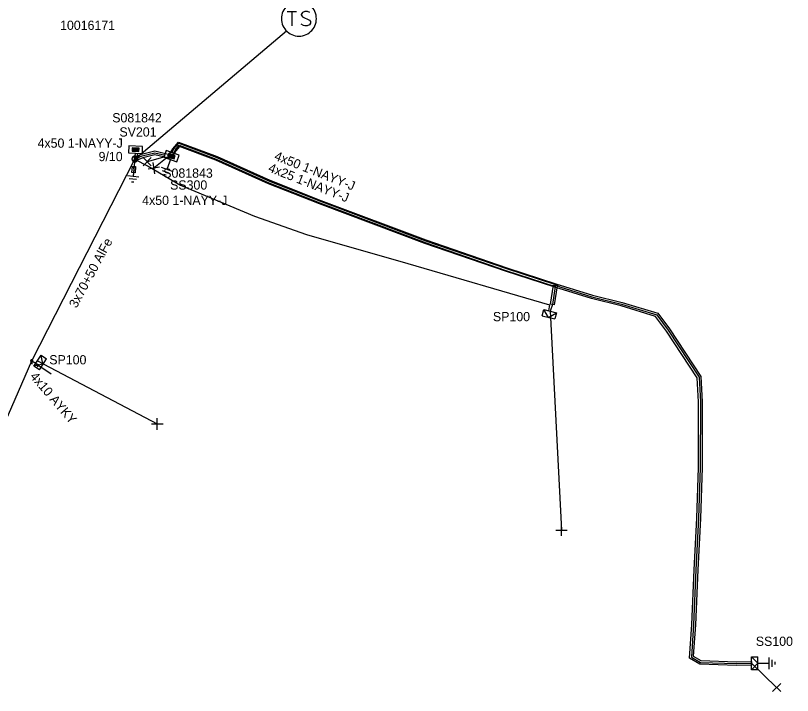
# Model space of a CAD drawing. Extents: x -717562 to -713845, y -1151196 to -1143903.
# Drawn here: x -717097.2 to -717013.1, y -1144090.6 to -1144017.1 of the extents above; entities that cross this region are included whole.
import ezdxf

# ---------------------------------------------------------------- set-up
doc = ezdxf.new("R2010")
doc.units = 0
for name, color, linetype in [('Vrstva 1', 7, 'Continuous'), ('Vrstva 12', 7, 'Continuous'), ('Vrstva 13', 7, 'Continuous'), ('Vrstva 14', 7, 'Continuous'), ('Vrstva 15', 7, 'Continuous'), ('Vrstva 16', 7, 'Continuous'), ('Vrstva 2', 7, 'Continuous'), ('Vrstva 20', 7, 'Continuous'), ('Vrstva 25', 7, 'Continuous'), ('Vrstva 26', 7, 'Continuous'), ('Vrstva 28', 7, 'Continuous'), ('Vrstva 29', 7, 'Continuous'), ('Vrstva 30', 7, 'Continuous'), ('Vrstva 31', 7, 'Continuous'), ('Vrstva 33', 7, 'Continuous'), ('Vrstva 34', 7, 'Continuous'), ('Vrstva 5', 7, 'Continuous'), ('Vrstva 52', 7, 'Continuous'), ('Vrstva 54', 7, 'Continuous'), ('Vrstva 59', 7, 'Continuous'), ('Vrstva 6', 7, 'Continuous'), ('Vrstva 8', 7, 'Continuous'), ('Vrstva 9', 7, 'Continuous')]:
    doc.layers.add(name, color=color, linetype=linetype)

# ---------------------------------------------------------------- blocks, each defined once
blk = doc.blocks.new('NN440')
at = {"layer": 'Vrstva 2'}
for points in [[(0.63, 0), (0.63, 0.06), (0.62, 0.13), (0.6, 0.19), (0.58, 0.25), (0.55, 0.31), (0.51, 0.37), (0.47, 0.42), (0.42, 0.46), (0.37, 0.51), (0.32, 0.54), (0.26, 0.57), (0.2, 0.59), (0.13, 0.61), (0.07, 0.62), (0, 0.63), (-0.06, 0.62), (-0.13, 0.61), (-0.19, 0.59), (-0.26, 0.57), (-0.31, 0.54), (-0.37, 0.51), (-0.42, 0.46), (-0.47, 0.42), (-0.51, 0.37), (-0.54, 0.31), (-0.57, 0.25), (-0.6, 0.19), (-0.62, 0.13), (-0.63, 0.06), (-0.63, 0), (-0.63, -0.07), (-0.62, -0.14), (-0.6, -0.2), (-0.57, -0.26), (-0.54, -0.32), (-0.51, -0.37), (-0.47, -0.43), (-0.42, -0.47), (-0.37, -0.51), (-0.31, -0.55), (-0.26, -0.58), (-0.19, -0.6), (-0.13, -0.62), (-0.06, -0.63), (0, -0.63), (0.07, -0.63), (0.13, -0.62), (0.2, -0.6), (0.26, -0.58), (0.32, -0.55), (0.37, -0.51), (0.42, -0.47), (0.47, -0.43), (0.51, -0.37), (0.55, -0.32), (0.58, -0.26), (0.6, -0.2), (0.62, -0.14), (0.63, -0.07), (0.63, 0)], [(-0.63, 0), (0.63, 0)], [(-0.6, -0.18), (0.57, -0.18)], [(-0.51, -0.32), (0.5, -0.32)], [(-0.37, -0.47), (0.35, -0.47)]]:
    blk.add_lwpolyline(points, dxfattribs=at)
blk = doc.blocks.new('NN565')
at = {"layer": 'Vrstva 2'}
for points in [[(0.015, 0.528), (0.015, 2.528)], [(0.157, 0.937), (0.015, 0.528), (-0.119, 0.937)]]:
    blk.add_lwpolyline(points, dxfattribs=at)
blk = doc.blocks.new('NN800')
at = {"layer": 'Vrstva 1'}
for points in [[(-0.442, 0.442), (0.442, -0.442)], [(-0.442, -0.442), (0.442, 0.442)]]:
    blk.add_lwpolyline(points, dxfattribs=at)
blk = doc.blocks.new('NN820')
at = {"layer": 'Vrstva 13'}
for points in [[(-0.003, 0.004), (-0.003, -1.049)], [(-0.165, -0.813), (0.165, -0.813)], [(-0.165, -1.473), (-0.165, -0.813)], [(0.165, -0.813), (0.165, -1.473)], [(0.165, -1.473), (-0.165, -1.473)], [(-0.003, -1.049), (-0.062, -0.926)], [(-0.003, -1.049), (0.057, -0.926)], [(-0.003, -1.473), (-0.003, -1.871)]]:
    blk.add_lwpolyline(points, dxfattribs=at)
blk = doc.blocks.new('NN620')
at = {"layer": 'Vrstva 8'}
for points in [[(0.752, 0.004), (-0.748, 0.004)], [(-0.748, 0.004), (-0.748, -0.746)], [(0.752, -0.746), (0.752, 0.004)], [(-0.748, -0.746), (0.752, -0.746)], [(0.368, -0.18), (-0.376, -0.18)], [(-0.376, -0.18), (-0.376, -0.558)], [(-0.376, -0.558), (0.368, -0.558)], [(0.321, -0.227), (-0.329, -0.227)], [(-0.329, -0.227), (-0.329, -0.51)], [(-0.329, -0.51), (0.321, -0.51)], [(0.274, -0.274), (-0.281, -0.274)], [(-0.281, -0.274), (-0.281, -0.463)], [(-0.281, -0.463), (0.274, -0.463)], [(0.227, -0.321), (-0.234, -0.321)], [(-0.234, -0.321), (-0.234, -0.416)], [(-0.234, -0.416), (0.227, -0.416)], [(-0.193, -0.369), (0.185, -0.369)], [(0.227, -0.416), (0.227, -0.321)], [(0.274, -0.463), (0.274, -0.274)], [(0.321, -0.51), (0.321, -0.227)], [(0.368, -0.558), (0.368, -0.18)]]:
    blk.add_lwpolyline(points, dxfattribs=at)
blk = doc.blocks.new('NN630')
at = {"layer": 'Vrstva 9'}
for points in [[(-0.003, -0.7), (-0.703, 0)], [(-0.703, -0.7), (-0.703, 0), (0.697, 0), (0.697, -0.7)], [(-0.703, -0.7), (0.697, -0.7)], [(-0.003, -0.7), (0.697, 0)]]:
    blk.add_lwpolyline(points, dxfattribs=at)
blk = doc.blocks.new('NN810')
at = {"layer": 'Vrstva 14'}
for points in [[(0.004, -0.64), (0.004, -1.89)], [(0.629, -1.89), (-0.621, -1.89)], [(0.388, -2.2), (-0.399, -2.2)], [(0.004, -2.515), (-0.124, -2.515)], [(0.137, -2.515), (0.004, -2.515)]]:
    blk.add_lwpolyline(points, dxfattribs=at)
blk = doc.blocks.new('NN500')
at = {"layer": 'Vrstva 2'}
for points in [[(0, -0.24), (0.02, -0.23), (0.05, -0.23), (0.07, -0.22), (0.09, -0.22), (0.12, -0.2), (0.14, -0.19), (0.16, -0.18), (0.17, -0.16), (0.19, -0.14), (0.2, -0.12), (0.21, -0.1), (0.22, -0.07), (0.23, -0.05), (0.23, -0.02), (0.23, 0), (0.23, 0.02), (0.23, 0.05), (0.22, 0.07), (0.21, 0.1), (0.2, 0.12), (0.19, 0.14), (0.17, 0.16), (0.16, 0.17), (0.14, 0.19), (0.12, 0.2), (0.09, 0.21), (0.07, 0.22), (0.05, 0.23), (0.02, 0.23), (0, 0.23), (-0.03, 0.23), (-0.05, 0.23), (-0.07, 0.22), (-0.1, 0.21), (-0.12, 0.2), (-0.14, 0.19), (-0.16, 0.17), (-0.18, 0.16), (-0.19, 0.14), (-0.2, 0.12), (-0.22, 0.1), (-0.22, 0.07), (-0.23, 0.05), (-0.23, 0.02), (-0.24, 0), (-0.23, -0.02), (-0.23, -0.05), (-0.22, -0.07), (-0.22, -0.1), (-0.2, -0.12), (-0.19, -0.14), (-0.18, -0.16), (-0.16, -0.18), (-0.14, -0.19), (-0.12, -0.2), (-0.1, -0.22), (-0.07, -0.22), (-0.05, -0.23), (-0.03, -0.23), (0, -0.24)], [(0, -0.24), (0.02, -0.23), (0.05, -0.23), (0.07, -0.22), (0.09, -0.22), (0.12, -0.2), (0.14, -0.19), (0.16, -0.18), (0.17, -0.16), (0.19, -0.14), (0.2, -0.12), (0.21, -0.1), (0.22, -0.07), (0.23, -0.05), (0.23, -0.02), (0.23, 0), (0.23, 0.02), (0.23, 0.05), (0.22, 0.07), (0.21, 0.1), (0.2, 0.12), (0.19, 0.14), (0.17, 0.16), (0.16, 0.17), (0.14, 0.19), (0.12, 0.2), (0.09, 0.21), (0.07, 0.22), (0.05, 0.23), (0.02, 0.23), (0, 0.23), (-0.03, 0.23), (-0.05, 0.23), (-0.07, 0.22), (-0.1, 0.21), (-0.12, 0.2), (-0.14, 0.19), (-0.16, 0.17), (-0.18, 0.16), (-0.19, 0.14), (-0.2, 0.12), (-0.22, 0.1), (-0.22, 0.07), (-0.23, 0.05), (-0.23, 0.02), (-0.24, 0), (-0.23, -0.02), (-0.23, -0.05), (-0.22, -0.07), (-0.22, -0.1), (-0.2, -0.12), (-0.19, -0.14), (-0.18, -0.16), (-0.16, -0.18), (-0.14, -0.19), (-0.12, -0.2), (-0.1, -0.22), (-0.07, -0.22), (-0.05, -0.23), (-0.03, -0.23), (0, -0.24)], [(0, -0.21), (0.02, -0.2), (0.04, -0.2), (0.06, -0.2), (0.08, -0.19), (0.1, -0.18), (0.12, -0.17), (0.14, -0.15), (0.15, -0.14), (0.16, -0.12), (0.18, -0.1), (0.19, -0.08), (0.19, -0.06), (0.2, -0.04), (0.2, -0.02), (0.2, 0), (0.2, 0.02), (0.2, 0.04), (0.19, 0.06), (0.19, 0.08), (0.18, 0.1), (0.16, 0.12), (0.15, 0.14), (0.14, 0.15), (0.12, 0.17), (0.1, 0.18), (0.08, 0.19), (0.06, 0.19), (0.04, 0.2), (0.02, 0.2), (0, 0.2), (-0.02, 0.2), (-0.04, 0.2), (-0.06, 0.19), (-0.08, 0.19), (-0.1, 0.18), (-0.12, 0.17), (-0.14, 0.15), (-0.15, 0.14), (-0.17, 0.12), (-0.18, 0.1), (-0.19, 0.08), (-0.2, 0.06), (-0.2, 0.04), (-0.21, 0.02), (-0.21, 0), (-0.21, -0.02), (-0.2, -0.04), (-0.2, -0.06), (-0.19, -0.08), (-0.18, -0.1), (-0.17, -0.12), (-0.15, -0.14), (-0.14, -0.15), (-0.12, -0.17), (-0.1, -0.18), (-0.08, -0.19), (-0.06, -0.2), (-0.04, -0.2), (-0.02, -0.2), (0, -0.21)], [(0, -0.18), (0.02, -0.18), (0.04, -0.17), (0.05, -0.17), (0.07, -0.16), (0.09, -0.15), (0.1, -0.14), (0.12, -0.13), (0.13, -0.12), (0.14, -0.1), (0.15, -0.09), (0.16, -0.07), (0.17, -0.05), (0.17, -0.04), (0.17, -0.02), (0.17, 0), (0.17, 0.02), (0.17, 0.04), (0.17, 0.05), (0.16, 0.07), (0.15, 0.09), (0.14, 0.1), (0.13, 0.12), (0.12, 0.13), (0.1, 0.14), (0.09, 0.15), (0.07, 0.16), (0.05, 0.17), (0.04, 0.17), (0.02, 0.17), (0, 0.18), (-0.02, 0.17), (-0.04, 0.17), (-0.06, 0.17), (-0.07, 0.16), (-0.09, 0.15), (-0.1, 0.14), (-0.12, 0.13), (-0.13, 0.12), (-0.14, 0.1), (-0.15, 0.09), (-0.16, 0.07), (-0.17, 0.05), (-0.17, 0.04), (-0.18, 0.02), (-0.18, 0), (-0.18, -0.02), (-0.17, -0.04), (-0.17, -0.05), (-0.16, -0.07), (-0.15, -0.09), (-0.14, -0.1), (-0.13, -0.12), (-0.12, -0.13), (-0.1, -0.14), (-0.09, -0.15), (-0.07, -0.16), (-0.06, -0.17), (-0.04, -0.17), (-0.02, -0.18), (0, -0.18)], [(0, -0.15), (0.01, -0.15), (0.03, -0.14), (0.04, -0.14), (0.06, -0.13), (0.07, -0.13), (0.08, -0.12), (0.1, -0.11), (0.11, -0.1), (0.12, -0.09), (0.13, -0.07), (0.13, -0.06), (0.14, -0.05), (0.14, -0.03), (0.14, -0.02), (0.14, 0), (0.14, 0.01), (0.14, 0.03), (0.14, 0.04), (0.13, 0.06), (0.13, 0.07), (0.12, 0.09), (0.11, 0.1), (0.1, 0.11), (0.08, 0.12), (0.07, 0.13), (0.06, 0.13), (0.04, 0.14), (0.03, 0.14), (0.01, 0.14), (0, 0.15), (-0.02, 0.14), (-0.03, 0.14), (-0.05, 0.14), (-0.06, 0.13), (-0.07, 0.13), (-0.09, 0.12), (-0.1, 0.11), (-0.11, 0.1), (-0.12, 0.09), (-0.13, 0.07), (-0.13, 0.06), (-0.14, 0.04), (-0.14, 0.03), (-0.15, 0.01), (-0.15, 0), (-0.15, -0.02), (-0.14, -0.03), (-0.14, -0.05), (-0.13, -0.06), (-0.13, -0.07), (-0.12, -0.09), (-0.11, -0.1), (-0.1, -0.11), (-0.09, -0.12), (-0.07, -0.13), (-0.06, -0.13), (-0.05, -0.14), (-0.03, -0.14), (-0.02, -0.15), (0, -0.15)], [(0, -0.12), (0.01, -0.12), (0.02, -0.11), (0.03, -0.11), (0.05, -0.11), (0.06, -0.1), (0.07, -0.09), (0.08, -0.09), (0.09, -0.08), (0.09, -0.07), (0.1, -0.06), (0.11, -0.05), (0.11, -0.04), (0.11, -0.02), (0.11, -0.01), (0.12, 0), (0.11, 0.01), (0.11, 0.02), (0.11, 0.04), (0.11, 0.05), (0.1, 0.06), (0.09, 0.07), (0.09, 0.08), (0.08, 0.09), (0.07, 0.09), (0.06, 0.1), (0.05, 0.11), (0.03, 0.11), (0.02, 0.11), (0.01, 0.12), (0, 0.12), (-0.01, 0.12), (-0.03, 0.11), (-0.04, 0.11), (-0.05, 0.11), (-0.06, 0.1), (-0.07, 0.09), (-0.08, 0.09), (-0.09, 0.08), (-0.1, 0.07), (-0.1, 0.06), (-0.11, 0.05), (-0.11, 0.04), (-0.12, 0.02), (-0.12, 0.01), (-0.12, 0), (-0.12, -0.01), (-0.12, -0.02), (-0.11, -0.04), (-0.11, -0.05), (-0.1, -0.06), (-0.1, -0.07), (-0.09, -0.08), (-0.08, -0.09), (-0.07, -0.09), (-0.06, -0.1), (-0.05, -0.11), (-0.04, -0.11), (-0.03, -0.11), (-0.01, -0.12), (0, -0.12)], [(0, -0.09), (0.01, -0.09), (0.02, -0.09), (0.03, -0.08), (0.03, -0.08), (0.04, -0.08), (0.05, -0.07), (0.06, -0.07), (0.06, -0.06), (0.07, -0.05), (0.07, -0.04), (0.08, -0.04), (0.08, -0.03), (0.08, -0.02), (0.09, -0.01), (0.09, 0), (0.09, 0.01), (0.08, 0.02), (0.08, 0.03), (0.08, 0.03), (0.07, 0.04), (0.07, 0.05), (0.06, 0.06), (0.06, 0.06), (0.05, 0.07), (0.04, 0.07), (0.03, 0.08), (0.03, 0.08), (0.02, 0.08), (0.01, 0.09), (0, 0.09), (-0.01, 0.09), (-0.02, 0.08), (-0.03, 0.08), (-0.04, 0.08), (-0.04, 0.07), (-0.05, 0.07), (-0.06, 0.06), (-0.07, 0.06), (-0.07, 0.05), (-0.08, 0.04), (-0.08, 0.03), (-0.08, 0.03), (-0.09, 0.02), (-0.09, 0.01), (-0.09, 0), (-0.09, -0.01), (-0.09, -0.02), (-0.08, -0.03), (-0.08, -0.04), (-0.08, -0.04), (-0.07, -0.05), (-0.07, -0.06), (-0.06, -0.07), (-0.05, -0.07), (-0.04, -0.08), (-0.04, -0.08), (-0.03, -0.08), (-0.02, -0.09), (-0.01, -0.09), (0, -0.09)], [(0, -0.06), (0, -0.06), (0.01, -0.06), (0.02, -0.05), (0.02, -0.05), (0.03, -0.05), (0.03, -0.05), (0.04, -0.04), (0.04, -0.04), (0.05, -0.03), (0.05, -0.03), (0.05, -0.02), (0.05, -0.02), (0.05, -0.01), (0.06, -0.01), (0.06, 0), (0.06, 0.01), (0.05, 0.01), (0.05, 0.02), (0.05, 0.02), (0.05, 0.03), (0.05, 0.03), (0.04, 0.04), (0.04, 0.04), (0.03, 0.05), (0.03, 0.05), (0.02, 0.05), (0.02, 0.05), (0.01, 0.06), (0, 0.06), (0, 0.06), (-0.01, 0.06), (-0.01, 0.06), (-0.02, 0.05), (-0.02, 0.05), (-0.03, 0.05), (-0.03, 0.05), (-0.04, 0.04), (-0.04, 0.04), (-0.05, 0.03), (-0.05, 0.03), (-0.05, 0.02), (-0.06, 0.02), (-0.06, 0.01), (-0.06, 0.01), (-0.06, 0), (-0.06, -0.01), (-0.06, -0.01), (-0.06, -0.02), (-0.05, -0.02), (-0.05, -0.03), (-0.05, -0.03), (-0.04, -0.04), (-0.04, -0.04), (-0.03, -0.05), (-0.03, -0.05), (-0.02, -0.05), (-0.02, -0.05), (-0.01, -0.06), (-0.01, -0.06), (0, -0.06)], [(0, -0.03), (0, -0.03), (0, -0.03), (0.01, -0.03), (0.01, -0.03), (0.01, -0.02), (0.02, -0.02), (0.02, -0.02), (0.02, -0.02), (0.02, -0.02), (0.02, -0.01), (0.02, -0.01), (0.03, -0.01), (0.03, -0.01), (0.03, 0), (0.03, 0), (0.03, 0), (0.03, 0.01), (0.03, 0.01), (0.02, 0.01), (0.02, 0.01), (0.02, 0.02), (0.02, 0.02), (0.02, 0.02), (0.02, 0.02), (0.01, 0.02), (0.01, 0.02), (0.01, 0.03), (0, 0.03), (0, 0.03), (0, 0.03), (0, 0.03), (-0.01, 0.03), (-0.01, 0.03), (-0.01, 0.02), (-0.02, 0.02), (-0.02, 0.02), (-0.02, 0.02), (-0.02, 0.02), (-0.02, 0.02), (-0.03, 0.01), (-0.03, 0.01), (-0.03, 0.01), (-0.03, 0.01), (-0.03, 0), (-0.03, 0), (-0.03, 0), (-0.03, -0.01), (-0.03, -0.01), (-0.03, -0.01), (-0.03, -0.01), (-0.02, -0.02), (-0.02, -0.02), (-0.02, -0.02), (-0.02, -0.02), (-0.02, -0.02), (-0.01, -0.03), (-0.01, -0.03), (-0.01, -0.03), (0, -0.03), (0, -0.03)], [(0.23, 0), (0.7, 0)]]:
    blk.add_lwpolyline(points, dxfattribs=at)
blk = doc.blocks.new('NN610')
at = {"layer": 'Vrstva 6'}
for points in [[(1.883, -0.001), (1.872, 0.196), (1.841, 0.392), (1.79, 0.583), (1.718, 0.768), (1.629, 0.943), (1.521, 1.109), (1.397, 1.263), (1.257, 1.403), (1.103, 1.527), (0.937, 1.635), (0.761, 1.725), (0.577, 1.796), (0.19, 1.878), (0.19, 1.878), (-0.007, 1.889), (-0.205, 1.878), (-0.401, 1.847), (-0.591, 1.796), (-0.777, 1.725), (-0.952, 1.635), (-1.118, 1.527), (-1.272, 1.403), (-1.412, 1.263), (-1.536, 1.109), (-1.644, 0.943), (-1.734, 0.768), (-1.805, 0.583), (-1.856, 0.392), (-1.887, 0.196), (-1.898, -0.001), (-1.887, -0.199), (-1.856, -0.395), (-1.805, -0.585), (-1.734, -0.77), (-1.644, -0.946), (-1.536, -1.112), (-1.411, -1.266), (-1.272, -1.405), (-1.118, -1.53), (-0.952, -1.638), (-0.776, -1.728), (-0.591, -1.799), (-0.401, -1.85), (-0.205, -1.881), (-0.007, -1.892), (0.19, -1.881), (0.385, -1.85), (0.577, -1.799), (0.761, -1.728), (0.937, -1.638), (1.103, -1.53), (1.257, -1.405), (1.397, -1.266), (1.521, -1.112), (1.629, -0.946), (1.718, -0.77), (1.79, -0.585), (1.841, -0.395), (1.872, -0.199), (1.883, -0.001)], [(-1.269, 0.782), (-0.261, 0.782)], [(-0.765, 0.782), (-0.765, -0.792)], [(1.188, 0.656), (0.936, 0.782), (0.621, 0.782), (0.369, 0.656), (0.243, 0.468), (0.243, 0.404), (0.369, 0.216), (1.125, -0.162), (1.251, -0.32), (1.251, -0.478), (1.125, -0.666), (0.873, -0.792), (0.621, -0.792), (0.495, -0.73), (0.243, -0.604)]]:
    blk.add_lwpolyline(points, dxfattribs=at)

msp = doc.modelspace()

# ---------------------------------------------------------------- linework, layer by layer
at = {"layer": 'Vrstva 1'}
for points in [[(-717084.26, -1144032.61), (-717067.847, -1144018.739)], [(-717137.335, -1144242.834), (-717130.537, -1144206.049), (-717125.876, -1144182.429), (-717122.246, -1144158.029), (-717113.166, -1144120.769), (-717112.247, -1144091.459), (-717102.297, -1144070.179), (-717095.416, -1144054.439), (-717084.26, -1144032.61)]]:
    msp.add_lwpolyline(points, dxfattribs=at)
at = {"layer": 'Vrstva 20'}
for points in [[(-717080.357, -1144031.856), (-717080.167, -1144031.497), (-717079.551, -1144030.774), (-717075.344, -1144032.345), (-717069.662, -1144034.906), (-717064.138, -1144037.083), (-717052.782, -1144041.352), (-717044.037, -1144044.37), (-717038.738, -1144046.09), (-717038.862, -1144046.47), (-717044.163, -1144044.75), (-717052.918, -1144041.728), (-717064.282, -1144037.457), (-717069.818, -1144035.274), (-717075.496, -1144032.715), (-717079.429, -1144031.246), (-717079.833, -1144031.723), (-717080.003, -1144032.044)], [(-717080.05, -1144032.102), (-717080.537, -1144032.518), (-717082.099, -1144032.146), (-717083.407, -1144032.47), (-717084.183, -1144032.795), (-717084.337, -1144032.425), (-717083.533, -1144032.09), (-717082.101, -1144031.734), (-717080.643, -1144032.082), (-717080.31, -1144031.798)], [(-717038.602, -1144046.31), (-717038.912, -1144048.36), (-717039.308, -1144048.3), (-717038.998, -1144046.25)], [(-717038.741, -1144046.089), (-717034.776, -1144047.317), (-717031.577, -1144048.117), (-717027.709, -1144049.277), (-717026.436, -1144050.985), (-717023.043, -1144056.135), (-717022.9, -1144058.875), (-717022.92, -1144065.984), (-717023.1, -1144071.468), (-717023.39, -1144077.039), (-717023.64, -1144082.971), (-717023.872, -1144086.369), (-717023.044, -1144086.842), (-717019.209, -1144086.98), (-717017.585, -1144086.94), (-717017.575, -1144087.34), (-717019.211, -1144087.38), (-717023.156, -1144087.238), (-717024.288, -1144086.591), (-717024.04, -1144082.949), (-717023.79, -1144077.021), (-717023.5, -1144071.452), (-717023.32, -1144065.976), (-717023.3, -1144058.885), (-717023.437, -1144056.265), (-717026.764, -1144051.215), (-717027.951, -1144049.623), (-717031.683, -1144048.503), (-717034.884, -1144047.703), (-717038.859, -1144046.471)]]:
    msp.add_lwpolyline(points, close=True, dxfattribs=at)
at = {"layer": 'Vrstva 5'}
for points in [[(-717080.18, -1144031.95), (-717080.083, -1144031.554), (-717079.521, -1144030.892), (-717075.382, -1144032.437), (-717069.701, -1144034.998), (-717064.174, -1144037.177), (-717052.816, -1144041.446), (-717044.068, -1144044.465), (-717038.769, -1144046.185), (-717038.296, -1144046.436), (-717034.83, -1144047.51), (-717031.63, -1144048.31), (-717027.83, -1144049.45), (-717026.6, -1144051.1), (-717023.24, -1144056.2), (-717023.1, -1144058.88), (-717023.12, -1144065.98), (-717023.3, -1144071.46), (-717023.59, -1144077.03), (-717023.84, -1144082.96), (-717024.08, -1144086.48), (-717023.1, -1144087.04), (-717019.21, -1144087.18), (-717017.58, -1144087.14)], [(-717080.004, -1144032.014), (-717079.917, -1144031.666), (-717079.459, -1144031.128), (-717075.458, -1144032.623), (-717069.779, -1144035.182), (-717064.246, -1144037.363), (-717052.884, -1144041.634), (-717044.132, -1144044.655), (-717038.815, -1144046.381), (-717039.11, -1144048.33), (-717039.35, -1144049.06)], [(-717084.26, -1144032.61), (-717084.194, -1144031.968)], [(-717083.983, -1144031.974), (-717084.029, -1144032.513), (-717083.47, -1144032.28), (-717082.1, -1144031.94), (-717080.98, -1144032.207)]]:
    msp.add_lwpolyline(points, dxfattribs=at)
at = {"layer": 'Vrstva 52'}
msp.add_lwpolyline([(-717095.416, -1144054.439), (-717094.956, -1144054.679), (-717094.786, -1144054.419)], dxfattribs=at)
at = {"layer": 'Vrstva 59'}
for points in [[(-717081.022, -1144032.373), (-717082.925, -1144032.903)], [(-717080.781, -1144032.446), (-717082.199, -1144033.593)], [(-717039.35, -1144049.06), (-717038.13, -1144072.75)], [(-717094.787, -1144054.419), (-717081.832, -1144061.263)], [(-717017.58, -1144087.14), (-717014.864, -1144089.754)]]:
    msp.add_lwpolyline(points, dxfattribs=at)
at = {"layer": 'Vrstva 9'}
msp.add_lwpolyline([(-717084.316, -1144032.629), (-717082.826, -1144033.369), (-717079.316, -1144035.419), (-717071.336, -1144038.779), (-717065.696, -1144040.779), (-717054.756, -1144043.919), (-717039.426, -1144048.369), (-717039.546, -1144049.009)], dxfattribs=at)

# ---------------------------------------------------------------- block references
at = {"layer": 'Vrstva 13', "xscale": 0.5}
for name, p, yscale, rotation in [('NN440', (-717084.26, -1144032.61), 0.4999999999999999, 56.133483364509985), ('NN500', (-717095.416, -1144054.439), 0.5, -90)]:
    msp.add_blockref(name, p, dxfattribs=dict(at, yscale=yscale, rotation=rotation))
at = {"layer": 'Vrstva 13', "rotation": -123.22082768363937}
msp.add_blockref('NN565', (-717095.417, -1144054.438), dxfattribs=at)
at = {"layer": 'Vrstva 15'}
for p, rotation in [((-717080.18, -1144031.95), -19.178997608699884), ((-717084.26, -1144032.61), -5.806166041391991), ((-717017.58, -1144087.14), 90.00000109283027)]:
    msp.add_blockref('NN810', p, dxfattribs=dict(at, rotation=rotation))
at = {"layer": 'Vrstva 16', "rotation": -5.806166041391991}
msp.add_blockref('NN820', (-717084.26, -1144032.61), dxfattribs=at)
at = {"layer": 'Vrstva 25'}
msp.add_blockref('NN610', (-717066.51, -1144017.43), dxfattribs=at)
at = {"layer": 'Vrstva 28'}
for p, rotation in [((-717084.194, -1144031.968), 178.2720383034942), ((-717080.18, -1144031.95), -19.178997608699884)]:
    msp.add_blockref('NN620', p, dxfattribs=dict(at, rotation=rotation))
at = {"layer": 'Vrstva 31'}
for p, rotation in [((-717039.35, -1144049.06), -13.869684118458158), ((-717094.786, -1144054.419), 56.779172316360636), ((-717017.58, -1144087.14), 90.00000109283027)]:
    msp.add_blockref('NN630', p, dxfattribs=dict(at, rotation=rotation))
at = {"layer": 'Vrstva 34'}
for p in [(-717082.925, -1144032.903), (-717014.864, -1144089.754)]:
    msp.add_blockref('NN800', p, dxfattribs=at)
for p, rotation in [((-717082.199, -1144033.593), 144.14878644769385), ((-717081.832, -1144061.264), 44.99999995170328), ((-717038.13, -1144072.75), 45)]:
    msp.add_blockref('NN800', p, dxfattribs=dict(at, rotation=rotation))

# ---------------------------------------------------------------- texts
at = {"layer": 'Vrstva 12'}
msp.add_text('9/10', height=1, dxfattribs=at).set_placement((-717088.184, -1144032.839))
at = {"layer": 'Vrstva 2'}
msp.add_text('3x70+50 AlFe', height=1, rotation=61.699, dxfattribs=at).set_placement((-717090.568, -1144048.8))
at = {"layer": 'Vrstva 26'}
msp.add_text('10016171', height=1, dxfattribs=at).set_placement((-717092.349, -1144018.644))
at = {"layer": 'Vrstva 29'}
for s, p in [('S081842', (-717086.706, -1144028.648)), ('S081843', (-717081.189, -1144034.632))]:
    msp.add_text(s, height=1, dxfattribs=at).set_placement(p)
at = {"layer": 'Vrstva 30'}
for s, p in [('SV201', (-717085.929, -1144030.177)), ('SS300', (-717080.45, -1144035.917))]:
    msp.add_text(s, height=1, dxfattribs=at).set_placement(p)
at = {"layer": 'Vrstva 33'}
for s, p in [('SP100', (-717045.542, -1144050.15)), ('SP100', (-717093.514, -1144054.819)), ('SS100', (-717017.113, -1144085.26))]:
    msp.add_text(s, height=1, dxfattribs=at).set_placement(p)
at = {"layer": 'Vrstva 54'}
msp.add_text('4x10 AYKY', height=1, rotation=310.605, dxfattribs=at).set_placement((-717095.668, -1144056.163))
at = {"layer": 'Vrstva 6'}
for p in [(-717094.781, -1144031.388), (-717083.469, -1144037.571)]:
    msp.add_text('4x50 1-NAYY-J', height=1, dxfattribs=at).set_placement(p)
for s, p in [('4x50 1-NAYY-J', (-717069.262, -1144032.661)), ('4x25 1-NAYY-J', (-717069.921, -1144033.938))]:
    msp.add_text(s, height=1, rotation=338.485, dxfattribs=at).set_placement(p)

doc.saveas('drawing.dxf')
